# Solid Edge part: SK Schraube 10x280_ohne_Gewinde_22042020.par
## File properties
Author: fknapp
Template: Normal.par
Last saved by: fknapp
Revision: 27
Application: Solid Edge
Username: fknapp
Material: Aluminium
Genauigkeit: 0,99
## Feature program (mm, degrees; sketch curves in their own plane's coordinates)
sketch for "unnamed RevolvedProtrusion 1" plane through (0, 0, 0) normal (0, 0, 1) x-axis (1, 0, 0)
  line (0, 54) -> (9, 54)
  line (9, 54) -> (9, 53)
  line (9, 53) -> (5, 49)
  line (5, 49) -> (5, 46.3)
  line (5, 46.3) -> (4.7548, 46.3)
  arc centre (4.7548, 44.6952) radius 1.6048 from (4.7548, 46.3) to (3.15, 44.6952) ccw
  line (3.15, 44.6952) -> (3.15, 42)
  line (3.15, 42) -> (5, 42)
  line (5, -213) -> (5, 42)
  line (0.5, -226) -> (5, -213)
  line (0, -226) -> (0.5, -226)
revolve "unnamed RevolvedProtrusion 1" add full turn 360 deg about sketch line (0, 54) -> (0, -226)
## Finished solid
Body 1: solid body, 11 faces, 10 edges, 0 vertices.
  Faces by surface: cylinder 4, plane 4, cone 2, torus 1
  Edges by curve: circle 10
Bounding box of the edges (mm; curved faces can reach further): 18.000 x 280.000 x 18.000, from (-9, -226, -9) to (9, 54, 9).
Cylindrical faces by radius (mm): R3.15 x1, R5 x2, R9 x1
Conical faces (half-angle, radius in mm at the cone's reference point): 19.0935 deg R5 x1, 45 deg R9 x1
Toroidal faces (ring radius, tube radius in mm): R4.7548 r1.6048 x1
Planar faces by outward normal: +y 2, -y 2
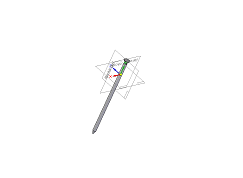
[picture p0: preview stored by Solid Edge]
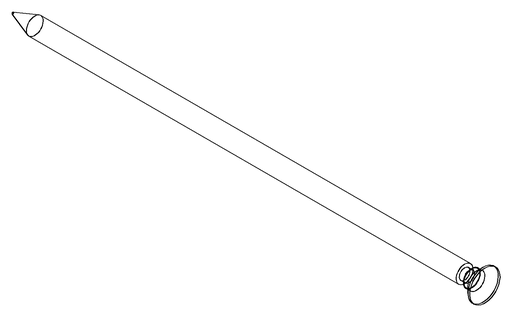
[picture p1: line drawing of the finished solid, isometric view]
